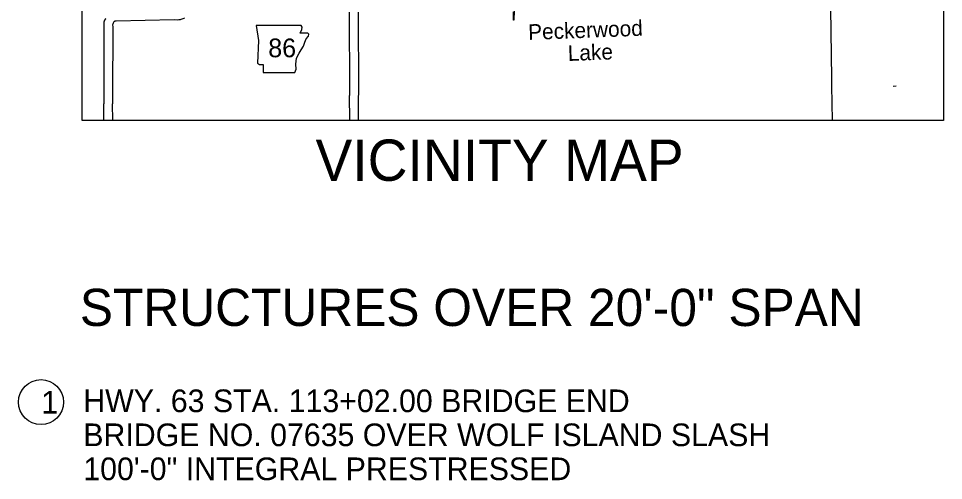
# Model space of a CAD drawing. Extents: x 982240 to 1103002, y 974866 to 1054902.
# Drawn here: x 983066 to 1006582, y 1023340 to 1035077 of the extents above; entities that cross this region are included whole.
import ezdxf

# ---------------------------------------------------------------- set-up
doc = ezdxf.new("R2010")
doc.units = 0
for name, color, linetype in [('21', 7, 'Continuous'), ('Default', 7, 'Continuous'), ('Level 10', 7, 'Continuous'), ('Level 15', 7, 'Continuous'), ('Level 2', 7, 'Continuous'), ('Level 21', 7, 'Continuous'), ('Level 9', 7, 'Continuous'), ('R_Draft', 7, 'Continuous')]:
    doc.layers.add(name, color=color, linetype=linetype)

msp = doc.modelspace()

# ---------------------------------------------------------------- linework, layer by layer
at = {"layer": 'Default'}
msp.add_line((1005381, 1033361), (1005299, 1033346), dxfattribs=at)
at = {"layer": 'Level 10'}
for points in [[(985283, 1035081), (985276, 1035067), (985255, 1035036), (985237, 1034986), (985234, 1034921), (985237, 1034860), (985232, 1033132), (985234, 1032910)], [(987284, 1035083), (987246, 1035068), (987220, 1035058), (987191, 1035050), (987175, 1035046), (987144, 1035042), (987098, 1035036), (987027, 1035040), (985551, 1035012), (985533, 1035010), (985526, 1035009), (985518, 1035006), (985506, 1035001), (985502, 1035000), (985494, 1034994), (985491, 1034992), (985489, 1034989), (985484, 1034980), (985472, 1034955), (985460, 1034937), (985459, 1034921), (985462, 1034864), (985457, 1033132), (985459, 1032912)], [(985238, 1032484), (985234, 1032910)], [(985463, 1032484), (985459, 1032912)]]:
    msp.add_lwpolyline(points, dxfattribs=at)
at = {"layer": 'Level 15'}
for points in [[(991475, 1035236), (991481, 1033219), (991484, 1033121)], [(991700, 1035237), (991706, 1033223), (991709, 1033128)], [(991488, 1032484), (991484, 1033123)], [(991713, 1032484), (991709, 1033125)]]:
    msp.add_lwpolyline(points, dxfattribs=at)
at = {"layer": 'Level 2'}
for points in [[(1003745, 1033554), (1003716, 1035338)], [(1003762, 1032484), (1003747, 1033368), (1003746, 1033551)]]:
    msp.add_lwpolyline(points, dxfattribs=at)
at = {"layer": 'Level 21'}
msp.add_lwpolyline([(989112, 1034898), (989169, 1034517), (989144, 1033940), (989195, 1033908), (989290, 1033908), (989290, 1033705), (990089, 1033705), (990127, 1033788), (990115, 1033921), (990134, 1034073), (990203, 1034194), (990248, 1034283), (990311, 1034378), (990349, 1034479), (990381, 1034562), (990438, 1034632), (990451, 1034676), (990425, 1034708), (990229, 1034708), (990273, 1034797), (990279, 1034854), (990253, 1034898)], close=True, dxfattribs=at)
at = {"layer": 'Level 9'}
msp.add_lwpolyline([(995666, 1035281), (995663, 1035038), (995650, 1035037), (995653, 1035244)], dxfattribs=at)
at = {"layer": 'R_Draft'}
msp.add_lwpolyline([(984683, 1051554), (1006582, 1051554), (1006582, 1032484), (984683, 1032484)], close=True, dxfattribs=at)
msp.add_circle((983638, 1025331), 572, dxfattribs=at)

# ---------------------------------------------------------------- texts
at = {"layer": '21'}
for s, p in [('HWY. 63 STA. 113+02.00 BRIDGE END ', (984713, 1025076)), ('BRIDGE NO. 07635 OVER WOLF ISLAND SLASH', (984713, 1024212)), ('100\'-0" INTEGRAL PRESTRESSED', (984713, 1023348))]:
    msp.add_text(s, height=576, dxfattribs=at).set_placement(p)
at = {"layer": 'Level 21'}
msp.add_text('86', height=475.2, dxfattribs=at).set_placement((989416, 1034093))
at = {"layer": 'Level 9'}
for s, p in [('Peckerwood', (996031, 1034533)), ('Lake', (997038, 1033998))]:
    msp.add_text(s, height=396, rotation=2.1229, dxfattribs=at).set_placement(p)
at = {"layer": 'R_Draft'}
for s, height, p in [('VICINITY MAP', 1050, (990616, 1030953)), ('1', 576, (983644, 1025040))]:
    msp.add_text(s, height=height, dxfattribs=at).set_placement(p)
msp.add_text('STRUCTURES OVER 20\'-0" SPAN', height=945, rotation=359.9958, dxfattribs=at).set_placement((984625, 1027266))

doc.saveas('drawing.dxf')
